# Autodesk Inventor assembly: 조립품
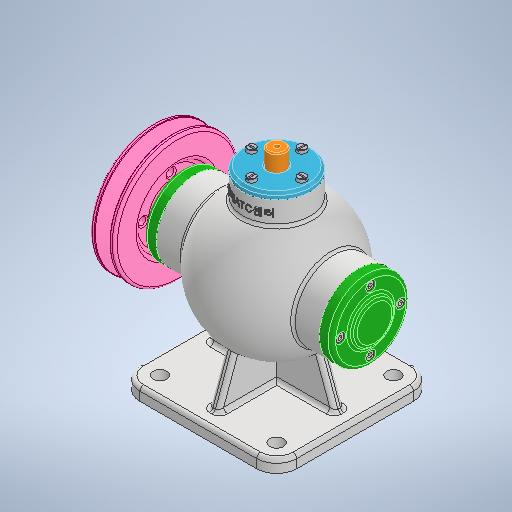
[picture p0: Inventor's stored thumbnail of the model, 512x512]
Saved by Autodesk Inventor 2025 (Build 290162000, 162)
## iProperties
Created: 2024-07
Part Number: 조립품
Document SubType Name: Assembly
Designer: Administrator
Author: Administrator
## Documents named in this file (15)
- C:\Users\Administrator\Desktop\740708V1003\740708V1003\조립품.iam
- C:\Users\Administrator\Desktop\740708V1003\본체.ipt
- C:\Users\Administrator\Desktop\740708V1003\740708V1003\뒤커버\뒤커버.ipt
- C:\Users\Administrator\Desktop\740708V1003\740708V1003\베어링- 6202\베어링- 6202.ipt
- C:\Users\Administrator\Desktop\740708V1003\740708V1003\볼트 M4 x 16\볼트 M4 x 16.ipt
- C:\Users\Administrator\Desktop\740708V1003\740708V1003\칼라\칼라.ipt
- C:\Users\Administrator\Desktop\740708V1003\740708V1003\앞커버\앞커버.ipt
- C:\Users\Administrator\Desktop\740708V1003\740708V1003\V-벨트풀리\V-벨트풀리.ipt
- C:\Users\Administrator\Desktop\740708V1003\740708V1003\너트 M8\너트 M8.ipt
- C:\Users\Administrator\Desktop\740708V1003\740708V1003\오일실 15 30 7\오일실 15 30 7.ipt
- C:\Users\Administrator\Desktop\740708V1003\740708V1003\키 4 x 4 x 12\키 4 x 4 x 12.ipt
- C:\Users\Administrator\Desktop\740708V1003\740708V1003\편심축\편심축.ipt
- C:\Users\Administrator\Desktop\740708V1003\740708V1003\볼트 M4 x 12\볼트 M4 x 12.ipt
- C:\Users\Administrator\Desktop\740708V1003\740708V1003\상부커버\상부커버.ipt
- C:\Users\Administrator\Desktop\740708V1003\740708V1003\슬라이드\슬라이드.ipt
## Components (1 placed, 1 different names)
1. V-벨트풀리:1
